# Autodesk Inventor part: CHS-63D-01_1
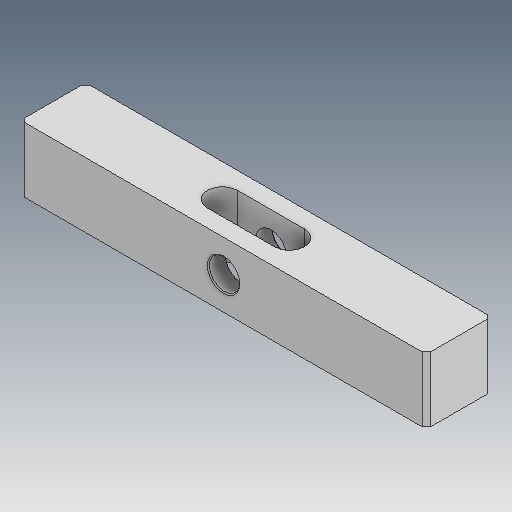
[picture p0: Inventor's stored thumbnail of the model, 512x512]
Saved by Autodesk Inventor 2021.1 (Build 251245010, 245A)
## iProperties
Created: 2019-05
Part Number: CHS-63D-01_1
Material: Ogólny
Document SubType Name: Modeling
Designer: user
Density: 1 g/cm^3
Appearance: Domyślna
Author: user
Revision Number: ÈÎºÎ
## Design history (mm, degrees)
feature "ÊäÈë1"
node "Bryła1"
